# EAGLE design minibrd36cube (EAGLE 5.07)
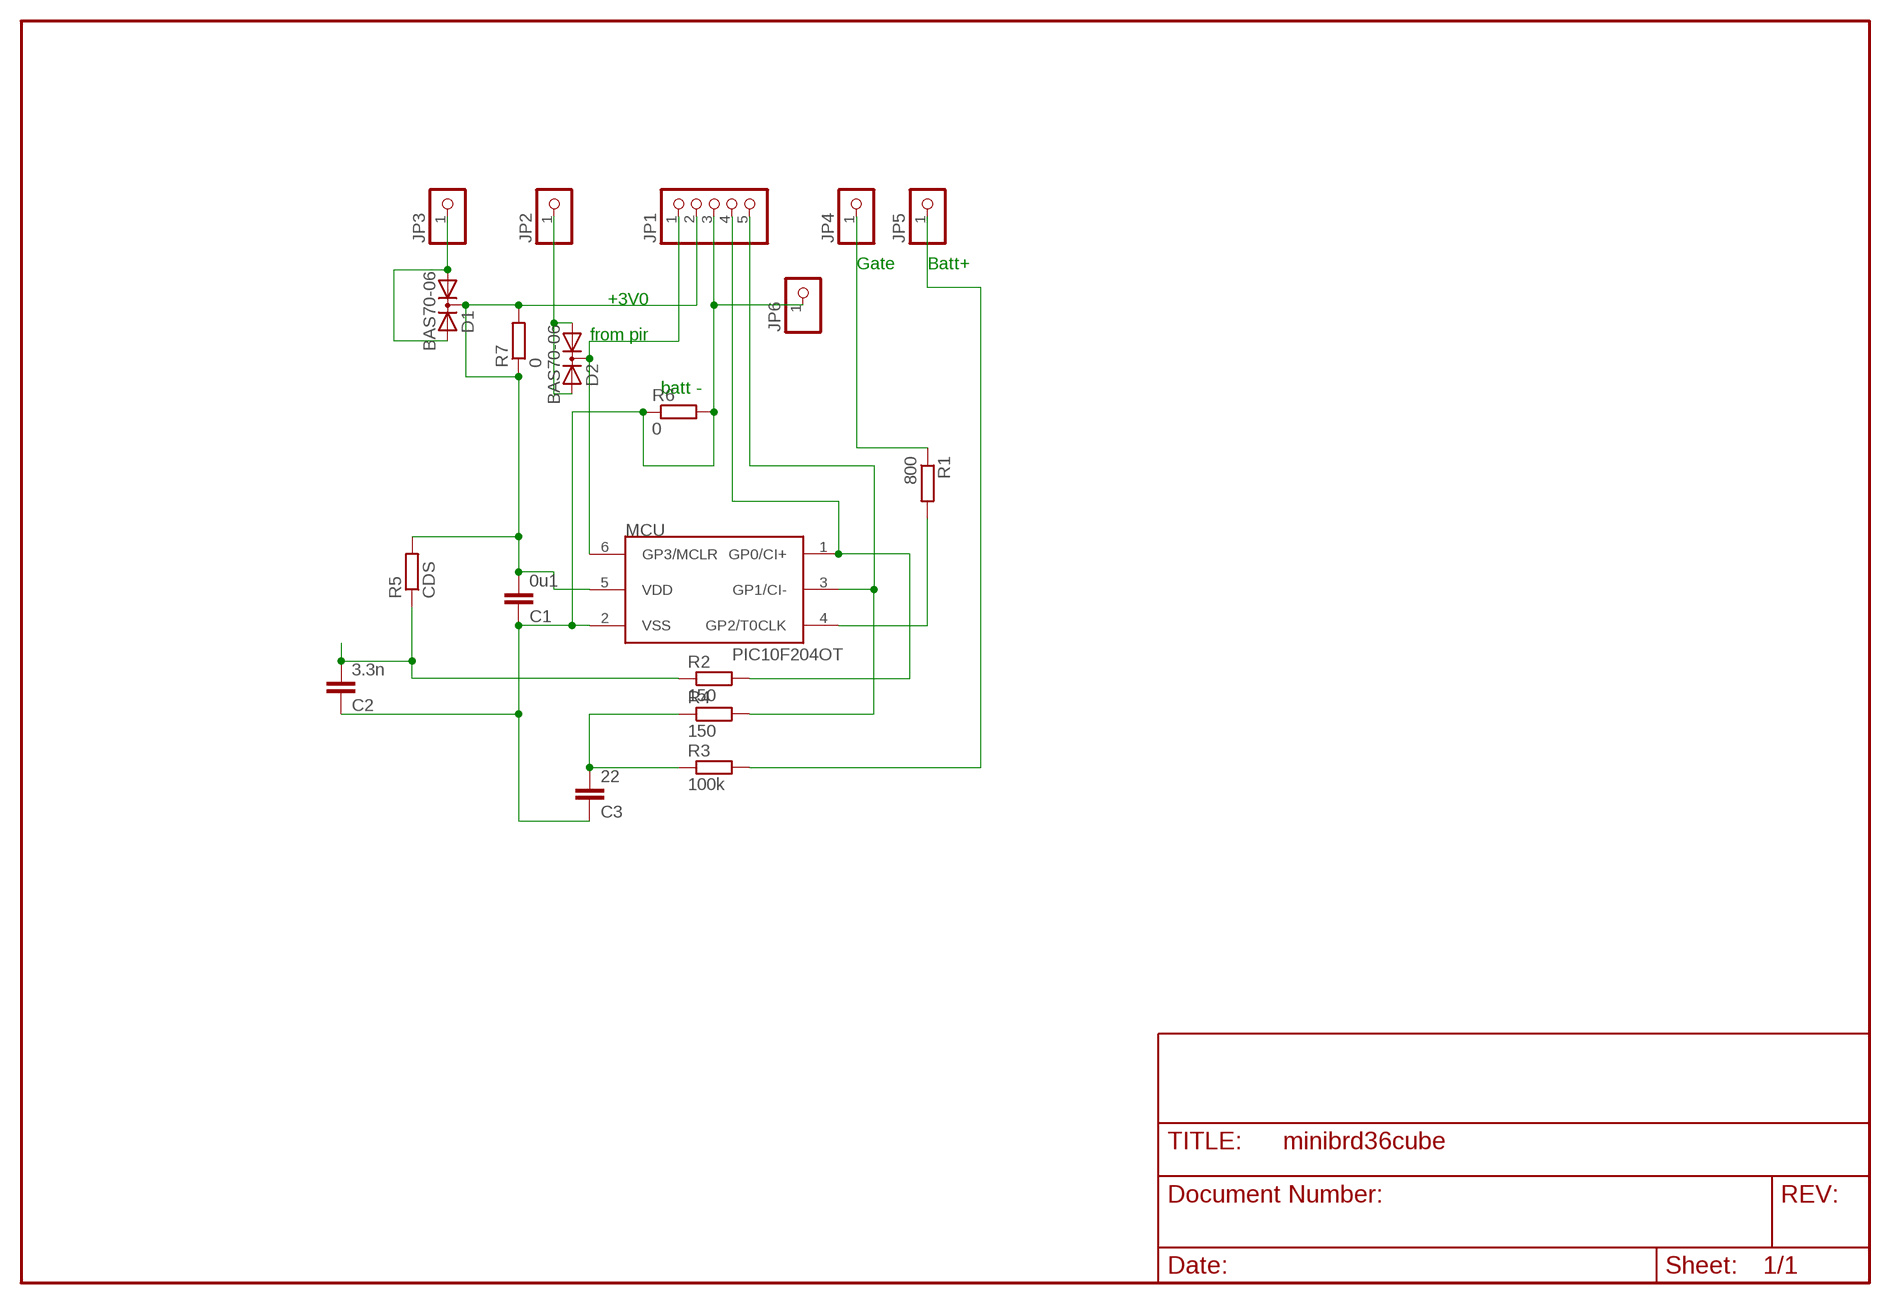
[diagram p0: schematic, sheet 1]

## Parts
C1  0u1  C-EUC1206  [C1206]
C2  3.3n  C-EUC1206  [C1206]
C3  22  C-EUC1206  [C1206]
D1  BAS70-06  [SOT23]
D2  BAS70-06  [SOT23]
JP1  PINHD-1X5  [1X05]
JP2  PINHD-1X1  [1X01]
JP3  PINHD-1X1  [1X01]
JP4  PINHD-1X1  [1X01]
JP5  PINHD-1X1  [1X01]
JP6  PINHD-1X1  [1X01]
MCU  PIC10F204OT  [SOT23-6]
R1  800  R-EU_R1206  [R1206]
R2  150  R-EU_R1206  [R1206]
R3  100k  R-EU_R1206  [R1206]
R4  150  R-EU_R1206  [R1206]
R5  CDS  R-EU_0613/5V  [P0613V]
R6  0  R-EU_R1206  [R1206]
R7  0  R-EU_R1206  [R1206]

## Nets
N$1: JP4.1 R1.1
N$2: C2.2 R2.1 R5.1
N$3: D1.1(A1) D1.2(A2) JP3.1
N$4: JP1.4 MCU.1(GP0/CI+) R2.2
N$5: MCU.4(GP2/T0CLK) R1.2
N$7: C3.2 R3.1 R4.1
N$8: JP1.5 MCU.3(GP1/CI-) R4.2
N$9: D2.1(A1) D2.2(A2) JP2.1
PIR: D2.3(C) JP1.1 MCU.6(GP3/MCLR)
V3: C1.2 D1.3(C) JP1.2 MCU.5(VDD) R5.2 R7.1 R7.2
V+: JP5.1 R3.2
V-: C1.1 C2.1 C3.1 JP1.3 JP6.1 MCU.2(VSS) R6.1 R6.2

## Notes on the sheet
- Gate | Batt+
- +3V0
- from pir
- batt -

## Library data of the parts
C1-C3 = rcl:C-EU: CAPACITOR, European symbol
D1 D2 = diode:BAS70-06: Silicon Schottky Diodes General-purpose diode for high-speed switching
JP1 = pinhead:PINHD-1X5: PIN HEADER
JP2-JP6 = pinhead:PINHD-1X1: PIN HEADER
MCU = microchip-3:PIC10F2*: uPC nW 0,25/0,5k Program Flash memory Comparator
R1-R7 = rcl:R-EU_: RESISTOR, European symbol

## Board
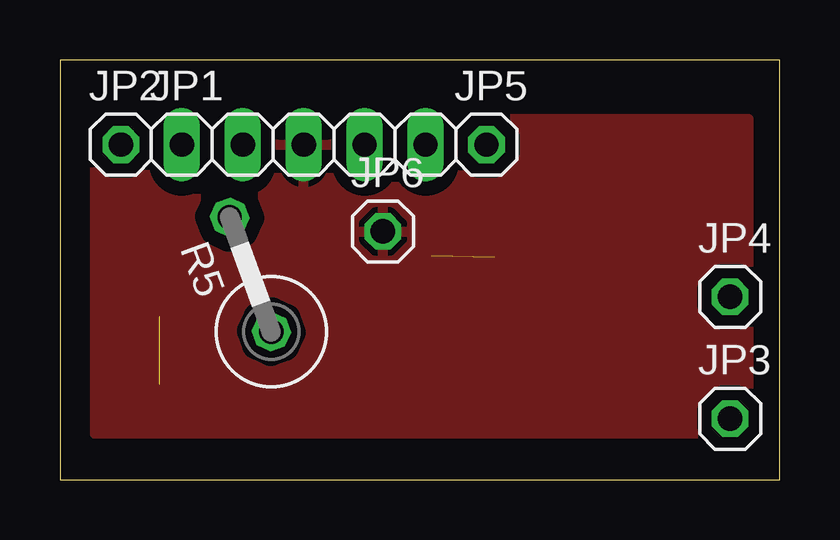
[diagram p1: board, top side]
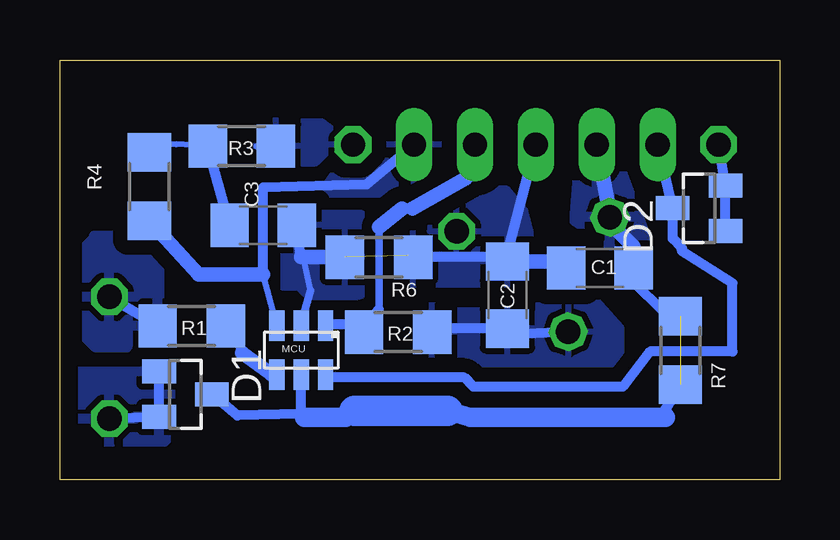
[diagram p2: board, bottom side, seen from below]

Size 30 x 17.5 mm. Coordinates in mm from the lower left corner, seen from the top.
Outline: 0,0 30,0 30,17.5 0,17.5 0,0
Copper layers (1*16): Top 0.035mm / dielectric 1.5mm / Bottom 0.035mm
Design rules "default": minimum track width 10mil, minimum drill 24mil, track to track 8mil, track to pad 8mil, pad to pad 8mil, via to via 8mil, smd to smd 8mil, copper to edge 1mil, drill to drill 8mil, minimum pad ring 10mil, minimum via ring 8mil, stop-mask expansion 4mil, vias tented up to drill 0mil, thermal gap 10mil

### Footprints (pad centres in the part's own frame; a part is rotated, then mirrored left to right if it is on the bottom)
C1206 = smd 1.6 x 1.8: 1 -1.4,0; 2 1.4,0
SOT23 = smd 1 x 1.4: 1 -0.95,-1.1; 2 0.95,-1.1; 3 0,1.1
1X05 = drill 1.016 long: 1 -5.08,0; 2 -2.54,0; 3 0,0; 4 2.54,0; 5 5.08,0
1X01 = drill 1.016 octagon: 1 0,0
SOT23-6 = smd 0.635 x 1.27: 1 -1.016,-1.016; 2 0,-1.016; 3 1.016,-1.016; 4 1.016,1.016; 5 0,1.016; 6 -1.016,1.016
R1206 = smd 1.6 x 1.803: 1 -1.422,0; 2 1.422,0
P0613V = drill 1.016 octagon: 1 -2.54,0; 2 2.54,0

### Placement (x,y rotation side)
C1  7.49,8.82 0 bottom
C2  11.34,7.69 270 bottom
C3  21.53,10.6 180 bottom
D1  24.77,3.56 270 bottom
D2  3.36,11.32 90 bottom
JP1  10.16,13.97 0 top
JP2  2.54,13.97 0 top
JP3  27.94,2.54 0 top
JP4  27.94,7.62 0 top
JP5  17.78,13.97 0 top
JP6  13.46,10.35 0 top
MCU  19.94,5.4 180 bottom
R1  24.5,6.41 0 bottom
R2  15.9,6.15 180 bottom
R3  22.42,13.91 0 bottom
R4  26.27,12.22 270 bottom
R5  7.94,8.55 110 top
R6  16.7,9.27 0 bottom
R7  4.14,5.39 270 bottom

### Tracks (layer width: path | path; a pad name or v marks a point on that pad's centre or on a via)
N$1
  Bottom 0.406: R1.1 JP4.1
  pour Bottom (isolate 0.61): 25.84,6.79 25.84,9.02 25.84,9.97 26.04,10.16 28.57,10.16 28.57,10.1 28.89,9.78 28.89,5.87 28.54,5.52 26.19,5.52 26.1,5.62
N$2
  Bottom 0.406: R5.1 11.49,6.03 11.49,6.29 C2.2 14.41,6.29 14.41,6.15 R2.1
  pour Bottom (isolate 0.61, rank 2): 8,7.94 9.78,7.94 10.22,7.05 13.27,7.05 15.11,7.49 15.24,4.57 7.24,4 6.6,4.51 6.6,6.35
N$3
  Bottom 0.406: JP3.1 D1.2 D1.1
  pour Bottom (isolate 0.61, rank 2): 25.4,5.08 28.8,5.08 29.05,4.83 29.05,2.19 28.45,1.59 25.62,1.59 25.34,1.87
N$4
  Bottom 0.305: 16.7,7.11 16.7,10.54
  Bottom 0.406: 13.09,12.56 JP1.4 | 15.75,11.3 15.3,11.3 | 17.18,6.57 17.27,6.48 18.8,6.48 18.92,6.35 MCU.1 | 17.18,6.57 16.7,7.11 | 17.18,6.57 | R2.2 17.32,6.27 17.18,6.57
  Bottom 0.61: 15.3,11.3 13.09,12.56 | 16.7,10.54 15.75,11.3
N$5
  Bottom 0.254: MCU.4 21.17,4.4 | 22.41,5.29 R1.2
  Bottom 0.61: 21.17,4.4 22.41,5.29
N$7
  Bottom 0.254: R3.1 25.14,13.98 25.96,13.95 R4.1
  Bottom 0.406: C3.2 R3.1
N$8
  Bottom 0.254: MCU.3 21.54,8.55
  Bottom 0.406: JP1.5 17.21,12.32 21.53,12.19 21.54,8.55
  Bottom 0.61: 21.54,8.55 24.23,8.55 R4.2
  pour Bottom (isolate 0.61): 13.78,14.03 15.49,11.87 19.37,11.87 18.73,12.57 17.65,14.16
N$9
  Bottom 0.406: JP2.1 D2.2 D2.1
PIR
  Bottom 0.406: MCU.6 18.92,4.25 13.14,4.25 12.76,3.87 6.54,3.87 5.4,5.33 1.97,5.33 1.97,8.19 4.06,9.53 4.06,9.65 4.46,10.04 D2.3 JP1.1
V3  (1 unrouted)
  Bottom 0.254: R5.2 7.18,11.11 7.14,11.41
  Bottom 0.406: 19.94,2.73 MCU.5 | 19.81,2.6 19.94,2.73 | 4.76,2.6 4.89,2.73 R7.2 | 6.09,9.2 6.03,9.14 | 6.09,9.2 C1.2 6.09,8.25 4.83,6.99 4.28,6.88 R7.1 | 6.1,9.72 6.1,9.21 6.09,9.2 | D1.3 22.61,2.67 19.94,2.73
  Bottom 0.61: R5.2 7.49,11.11 6.1,9.72 | 7.14,11.41 JP1.2
  Bottom 0.813: 4.76,2.6 12.89,2.6 13.84,2.86 | 17.72,2.86 18.1,2.6 19.81,2.6
  Bottom 1.27: 13.84,2.86 17.72,2.86
  pour Bottom: 8.38,13.14 8.57,10.79 6.79,9.53 5.33,9.59 6.67,13.14
V+
  Bottom 0.254: 21.32,13.9 21.82,13.9 R3.2
  pour Bottom (isolate 0.61): 19.05,14.92 21.84,14.99 21.84,12.26 20.38,12.13 18.22,14.29
V-  (1 unrouted)
  Bottom 0.254: 19.55,7.88 C3.1 | MCU.2 19.88,6.73
  Bottom 0.305: 19.88,6.73 19.55,7.88
  Bottom 0.406: 19.94,9.27 20,9.33 C3.1 | C2.1 11.29,9.1 11.24,9.14 11.38,9.29 | 11.38,9.29 JP1.3 | C1.1 8.96,9.2 9.07,9.1 | 15.45,9.29 15.43,9.27 R6.2 | 11.38,9.29 15.45,9.29 | 15.45,9.29 15.49,9.34
  Bottom 0.61: 19.94,9.27 R6.1 | 9.07,9.1 C2.1
  pour Bottom (isolate 0.61): 11.37,12.13 12.76,12.13 13.27,12.06 14.67,10.67 14.92,10.67 15.75,9.84 15.75,8.13 10.35,8.13 10.35,10.22 10.6,11.24
  pour Bottom (isolate 0.406): 17.4,11.11 20.19,11.11 20.7,10.6 20.7,8 20.07,8 19.68,7.62 17.59,7.62 17.4,7.68
  pour Top (isolate 0.61): 1.71,15.05 28.7,15.05 28.7,1.91 1.46,1.91 1.46,14.35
